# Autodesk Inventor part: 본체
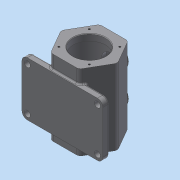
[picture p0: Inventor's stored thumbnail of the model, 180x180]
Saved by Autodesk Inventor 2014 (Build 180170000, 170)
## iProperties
Created: 2021-06
Part Number: 본체
Material: 일반
Document SubType Name: Modeling
Designer: net
Density: 1 g/cm^3
Appearance: 기본값
Author: net
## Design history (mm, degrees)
sketch "스케치2" dims "d3" = 105
  geometry: L1 (-52.5, 0)-(-26.25, 45.466); L2 (-26.25, 45.466)-(26.25, 45.466); L3 (26.25, 45.466)-(52.5, 0); L4 (52.5, 0)-(26.25, -45.466); L5 (26.25, -45.466)-(-26.25, -45.466); L6 (-26.25, -45.466)-(-52.5, 0); 4 further points
  constraints: 12 end point, 2 coincident, 1 horizontal alignment, 1 midpoint, 1 vertical alignment, 15 other
extrude "돌출1" new body sketch "스케치2" stored distance "d4" = 140; taper "d5" = 0 deg
node "작업 평면1"
sketch "스케치3" dims "d82" = 3
  geometry: L1 (75, 45)-(-75, 45); L2 (-75, 45)-(-75, -55); L3 (-75, -55)-(75, -55); L4 (75, -55)-(75, 45); L5 (26.25, 70)-(52.5, 70) reference; L6 (52.5, -70)-(26.25, -70) reference; 2 further points
  constraints: 8 end point, 2 parallel, 1 horizontal, 1 midpoint, 1 perpendicular, 1 vertical alignment
  dimensions: "d7" = 25 distance between parallel lines of L1 L5; "d8" = 15 distance between parallel lines of L6 L3; "d9" = 150 distance between parallel lines of L2 L4
extrude "돌출2" join sketch "스케치3" distance "d10" = 12; taper "d11" = 0 deg
fillet "모깎기1" dims "d12" = 10
sketch "스케치4"
  geometry: C1 r 5.5 at (-65, 45); C2 r 5.5 at (-65, -35); A1 r 10 centre (-65, 45) between (-65, 55) and (-75, 45) reference; A2 r 10 centre (-65, -35) between (-75, -35) and (-65, -45) reference; 1 further point
  constraints: 2 centre point, 2 coincident
  dimensions: "d13" = 11 diameter of C1; "d14" = 11 diameter of C2
extrude "돌출3" cut sketch "스케치4" stored distance "d15" = 12; taper "d16" = 0 deg
sketch "스케치5"
  geometry: L1 (45.466, 70)-(0, 70) reference; L2 (0, 70)-(-45.466, 70) reference; L3 (-45.466, 70)-(0, 70) reference; L4 (0, 70)-(45.466, 70) reference; L5 (0, -70)-(45.466, -70) reference; L6 (45.466, -70)-(0, -70) reference; L7 (0, -70)-(-45.466, -70) reference; L8 (-45.466, -70)-(0, -70) reference; L9 (0, 70)-(30, 70); L10 (30, 58)-(37.5, 58); L11 (37.5, 58)-(37.5, -58); L12 (37.5, -58)-(30, -58); L13 (30, 58)-(30, 70); L14 (0, 70)-(0, -70); L15 (30, -58)-(30, -70); L16 (30, -70)-(0, -70); 1 further point
  constraints: 16 end point, 2 parallel, 2 perpendicular, 2 point on line
  dimensions: "d17" = 60 diameter of L13 L14; "d18" = 75 diameter of L11 L14; "d20" = 12 distance of L10.start L9.end; "d21" = 12 distance of L12.end L15.end; "d22" = 60 diameter of L15 L14; "d23" = 12 distance from line of L1 L10.end
revolve "회전1" sketch "스케치5" stored, may be unused: angle "d24" = 90 deg
sketch "스케치8"
  geometry: L1 (52.5, 0)-(26.25, 45.466) reference; L2 (26.25, 45.466)-(-26.25, 45.466) reference; L3 (0, 45.466)-(0, 0); L4 (0, 0)-(33.284, 33.284); C1 r 30 at (0, 0) reference; 1 further point
  constraints: 4 end point, 2 point on line, 1 midpoint
  dimensions: "d39" = 45 deg angle of L4 L3; "d40" = 40 distance of L3.end point (28.284, 28.284)
hole "구멍2" sketch "스케치8" at (28.284, 28.284) diameter "d41" = 3.459; stored, may be unused: countersink angle "d45" = 90 deg, drill point angle "d47" = 118 deg; dims "d42" = 8, "d43" = 4, "d44" = 2, "d46" = 10
sketch "스케치9"
  geometry: C1 r 30 at (0, 0) reference; 1 further point
  constraints: 1 vertical alignment
  dimensions: "d51" = 40 distance of C1.centre point (0, 40)
hole "구멍3" sketch "스케치9" at (0, 40) diameter "d52" = 3.459; stored, may be unused: countersink angle "d56" = 90 deg, drill point angle "d58" = 118 deg; dims "d53" = 8, "d54" = 4, "d55" = 2, "d57" = 10
node "작업 평면2"
sketch "스케치11"
  geometry: L1 (-26.25, 70)-(26.25, 70) reference; C1 r 20 at (0, 30); C2 r 20 at (0, -30); 2 further points
  constraints: 2 centre point, 2 vertical alignment, 1 midpoint
  dimensions: "d67" = 40 distance of point (0, 70) C1.centre; "d68" = 60 distance of C2.centre C1.centre; "d69" = 40 diameter of C1; "d70" = 40 diameter of C2
extrude "돌출4" join sketch "스케치11" stored distance "d71" = 12; taper "d72" = 0 deg
sketch "스케치12"
  geometry: C1 r 20 at (0, 0) reference; C2 r 15 at (0, 0); C3 r 20 at (0, 60) reference; C4 r 15 at (0, 60); 1 further point
  constraints: 2 centre point, 2 coincident
  dimensions: "d73" = 30 diameter of C2; "d74" = 30 diameter of C4
extrude "돌출5" cut sketch "스케치12" distance "d75" = 8; taper "d76" = 0 deg
sketch "스케치13"
  geometry: C1 r 15 at (0, 0) reference; C2 r 12.5 at (0, 0); C3 r 15 at (0, 60) reference; C4 r 12.5 at (0, 60); 1 further point
  constraints: 2 centre point, 2 coincident
  dimensions: "d77" = 25 diameter of C2; "d78" = 25 diameter of C4
extrude "돌출6" cut sketch "스케치13" stored distance "d79" = 8; taper "d80" = 0 deg
fillet "모깎기2" dims "d81" = 8
fillet "모깎기3" dims "d82" = 3
fillet "모깎기4" dims "d83" = 3
fillet "모깎기5" dims "d84" = 3
chamfer "모따기1" distance "d85" = 1; stored, may be unused: second distance "d86" = 2, angle "d87" = 45 deg
sketch "스케치14"
  geometry: L1 (-65, -45)-(-32.293, -45) reference; L2 (-75, 45)-(-75, -35) reference; 2 further points
  constraints: 1 other
  dimensions: "d88" = 50 distance from line of L1 point (-61, 5); "d89" = 14 distance from line of L2 point (-61, 5)
feature "엠보싱1" sketch "스케치14" dims "d3" = 105, "d90" = 0.5, "d91" = 0
node "솔리드1"
mirror "대칭1"
pattern_circular "원형 패턴2" dims angle "d49" = 360 deg
pattern_circular "원형 패턴3" dims angle "d60" = 360 deg
node "투영된 루프1"
node "투영된 루프2"
other parameters: "d66" = 52.5
